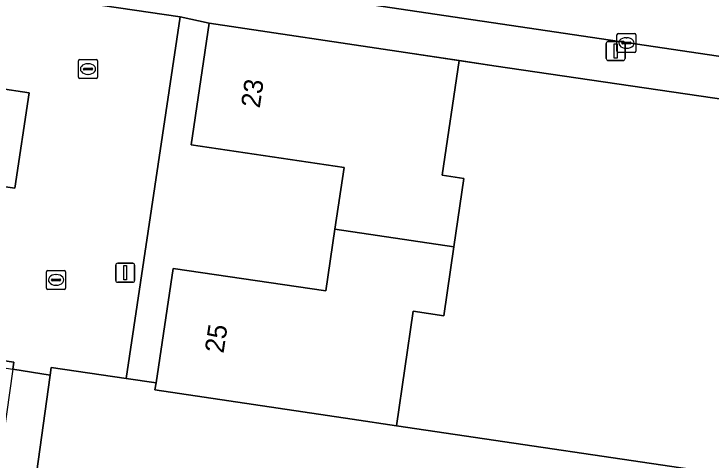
# Model space of a CAD drawing. Extents: x 164148 to 165261, y 382513 to 383432.
# Drawn here: x 164395.92 to 164432.53, y 383053.88 to 383077.34 of the extents above; entities that cross this region are included whole.
import ezdxf

# ---------------------------------------------------------------- set-up
doc = ezdxf.new("R2010")
doc.units = 0
for name, color, linetype in [('IMGEO_Erf', 7, 'Continuous'), ('IMGEO_Fietspad_gesloten', 7, 'Continuous'), ('IMGEO_Groenvoorziening', 7, 'Continuous'), ('IMGEO_Hek', 7, 'Continuous'), ('IMGEO_Kolk', 7, 'Continuous'), ('IMGEO_Lichtmast', 7, 'Continuous'), ('IMGEO_Muur', 7, 'Continuous'), ('IMGEO_Pand', 7, 'Continuous'), ('IMGEO_Pand_nummerreeks', 7, 'Continuous'), ('IMGEO_Parkeervlak_open', 7, 'Continuous'), ('IMGEO_Rijbaan_lokaal_open', 7, 'Continuous'), ('IMGEO_Voetpad_open', 7, 'Continuous')]:
    doc.layers.add(name, color=color, linetype=linetype)

msp = doc.modelspace()

# ---------------------------------------------------------------- linework, layer by layer
at = {"layer": 'IMGEO_Erf'}
msp.add_lwpolyline([(164408.851, 383199.365), (164399.172, 383200.803), (164378.916, 383061.2), (164379.681, 383061.088), (164380.615, 383067.448), (164390.499, 383065.99), (164389.565, 383059.634), (164395.869, 383058.657), (164395.922, 383059.034), (164391.378, 383059.698), (164394.192, 383078.726), (164411.436, 383195.306)], dxfattribs=at)
for points in [[(164401.814, 383058.173), (164403.383, 383057.94), (164404.276, 383063.953), (164412.299, 383062.781), (164412.78, 383066.02), (164413.261, 383069.26), (164405.229, 383070.453), (164406.174, 383076.848), (164404.649, 383077.179)], [(164434.53, 383066.472), (164436.024, 383066.259), (164436.915, 383072.291), (164421.248, 383074.597), (164419.302, 383074.895), (164418.405, 383068.862), (164419.551, 383068.692), (164419.029, 383065.092), (164418.504, 383061.473), (164416.89, 383061.707), (164416.017, 383055.69), (164434.025, 383053.023), (164434.924, 383059.038), (164433.441, 383059.262), (164433.985, 383062.865)]]:
    msp.add_lwpolyline(points, close=True, dxfattribs=at)
at = {"layer": 'IMGEO_Fietspad_gesloten'}
msp.add_lwpolyline([(164397.822, 383058.341), (164395.869, 383058.657), (164394.396, 383048.32), (164396.385, 383048.006)], close=True, dxfattribs=at)
at = {"layer": 'IMGEO_Groenvoorziening'}
msp.add_lwpolyline([(164416.017, 383055.69), (164413.688, 383056.036), (164403.328, 383057.574), (164403.383, 383057.94), (164401.814, 383058.173), (164397.879, 383058.748), (164397.822, 383058.341), (164396.385, 383048.006), (164450.7, 383039.958), (164452.315, 383050.297), (164452.362, 383050.597), (164448.44, 383051.183), (164446.886, 383051.412), (164446.845, 383051.128), (164434.025, 383053.023)], close=True, dxfattribs=at)
at = {"layer": 'IMGEO_Hek'}
msp.add_lwpolyline([(164413.688, 383056.036), (164434.025, 383053.023)], dxfattribs=at)
at = {"layer": 'IMGEO_Kolk'}
for p, q in [((164427.586, 383075.382), (164427.586, 383076.234)), ((164427.661, 383076.308), (164428.513, 383076.308)), ((164428.587, 383076.234), (164428.587, 383075.382)), ((164427.888, 383075.851), (164428.286, 383075.851)), ((164428.074, 383076.088), (164428.099, 383076.088)), ((164427.845, 383075.802), (164427.845, 383075.814)), ((164428.283, 383075.765), (164427.885, 383075.765)), ((164428.097, 383075.528), (164428.072, 383075.528)), ((164428.329, 383075.814), (164428.329, 383075.802)), ((164428.513, 383075.308), (164427.661, 383075.308)), ((164399.311, 383074.014), (164399.311, 383074.866)), ((164399.386, 383074.94), (164400.238, 383074.94)), ((164400.312, 383074.866), (164400.312, 383074.014)), ((164399.57, 383074.434), (164399.57, 383074.446)), ((164400.008, 383074.397), (164399.61, 383074.397)), ((164399.613, 383074.483), (164400.011, 383074.483)), ((164399.799, 383074.72), (164399.824, 383074.72)), ((164400.054, 383074.446), (164400.054, 383074.434)), ((164399.822, 383074.16), (164399.797, 383074.16)), ((164400.238, 383073.94), (164399.386, 383073.94)), ((164397.632, 383062.929), (164397.632, 383063.781)), ((164397.707, 383063.855), (164398.559, 383063.855)), ((164398.633, 383063.781), (164398.633, 383062.929)), ((164397.934, 383063.398), (164398.332, 383063.398)), ((164398.12, 383063.635), (164398.145, 383063.635)), ((164397.891, 383063.349), (164397.891, 383063.361)), ((164398.329, 383063.312), (164397.931, 383063.312)), ((164398.143, 383063.075), (164398.118, 383063.075)), ((164398.375, 383063.361), (164398.375, 383063.349)), ((164398.559, 383062.855), (164397.707, 383062.855))]:
    msp.add_line(p, q, dxfattribs=at)
for points in [[(164427.586, 383075.382), (164427.586, 383076.234)], [(164427.661, 383076.308), (164428.513, 383076.308)], [(164428.587, 383076.234), (164428.587, 383075.382)], [(164428.513, 383075.308), (164427.661, 383075.308)], [(164399.311, 383074.014), (164399.311, 383074.866)], [(164399.386, 383074.94), (164400.238, 383074.94)], [(164400.312, 383074.866), (164400.312, 383074.014)], [(164400.238, 383073.94), (164399.386, 383073.94)], [(164397.632, 383062.929), (164397.632, 383063.781)], [(164397.707, 383063.855), (164398.559, 383063.855)], [(164398.633, 383063.781), (164398.633, 383062.929)], [(164398.559, 383062.855), (164397.707, 383062.855)]]:
    msp.add_lwpolyline(points, dxfattribs=at)
for centre, radius, start, end in [((164427.663, 383076.232), 0.0765, 91.552, 178.448), ((164427.663, 383076.232), 0.0765, 91.552, 178.448), ((164428.511, 383076.232), 0.0765, 1.552, 88.448), ((164428.511, 383076.232), 0.0765, 1.552, 88.448), ((164427.885, 383075.811), 0.0403, 85.8775, 175.7526), ((164428.29, 383075.813), 0.0386, 1.7309, 96.639), ((164427.882, 383075.801), 0.0366, 178.938, 274.7102), ((164428.286, 383075.808), 0.043, 264.8664, 352.4533), ((164427.663, 383075.384), 0.0765, 181.552, 268.448), ((164427.663, 383075.384), 0.0765, 181.552, 268.448), ((164428.511, 383075.384), 0.0765, 271.552, 358.448), ((164428.511, 383075.384), 0.0765, 271.552, 358.448), ((164399.388, 383074.864), 0.0765, 91.552, 178.448), ((164399.388, 383074.864), 0.0765, 91.552, 178.448), ((164400.236, 383074.864), 0.0765, 1.552, 88.448), ((164400.236, 383074.864), 0.0765, 1.552, 88.448), ((164399.61, 383074.443), 0.0403, 85.8775, 175.7526), ((164399.607, 383074.433), 0.0366, 178.938, 274.7102), ((164400.011, 383074.44), 0.043, 264.8664, 352.4533), ((164400.015, 383074.445), 0.0386, 1.7309, 96.639), ((164399.388, 383074.016), 0.0765, 181.552, 268.448), ((164399.388, 383074.016), 0.0765, 181.552, 268.448), ((164400.236, 383074.016), 0.0765, 271.552, 358.448), ((164400.236, 383074.016), 0.0765, 271.552, 358.448), ((164397.709, 383063.779), 0.0765, 91.552, 178.448), ((164397.709, 383063.779), 0.0765, 91.552, 178.448), ((164398.557, 383063.779), 0.0765, 1.552, 88.448), ((164398.557, 383063.779), 0.0765, 1.552, 88.448), ((164397.931, 383063.358), 0.0403, 85.8775, 175.7526), ((164398.336, 383063.36), 0.0386, 1.7309, 96.639), ((164397.928, 383063.348), 0.0366, 178.938, 274.7102), ((164398.332, 383063.355), 0.043, 264.8664, 352.4533), ((164397.709, 383062.931), 0.0765, 181.552, 268.448), ((164397.709, 383062.931), 0.0765, 181.552, 268.448), ((164398.557, 383062.931), 0.0765, 271.552, 358.448), ((164398.557, 383062.931), 0.0765, 271.552, 358.448)]:
    msp.add_arc(centre, radius, start, end, dxfattribs=at)
for centre, major_axis, ratio, start_param, end_param in [((164428.073, 383075.808), (-0.387, 0.002), 0.722429, 4.712389, 7.853982), ((164428.098, 383075.808), (-0.39, 0.002), 0.717154, 1.570796, 4.712389), ((164399.798, 383074.44), (-0.387, 0.002), 0.722429, 4.712389, 7.853982), ((164399.823, 383074.44), (-0.39, 0.002), 0.717154, 1.570796, 4.712389), ((164398.119, 383063.355), (-0.387, 0.002), 0.722429, 4.712389, 7.853982), ((164398.144, 383063.355), (-0.39, 0.002), 0.717154, 1.570796, 4.712389)]:
    msp.add_ellipse(centre, major_axis=major_axis, ratio=ratio, start_param=start_param, end_param=end_param, dxfattribs=at)
at = {"layer": 'IMGEO_Lichtmast'}
for p, q in [((164427.124, 383075.889), (164427.914, 383075.889)), ((164427.914, 383075.889), (164427.124, 383075.889)), ((164427.024, 383074.989), (164427.024, 383075.789)), ((164427.024, 383075.789), (164427.024, 383074.989)), ((164428.014, 383075.789), (164428.014, 383074.989)), ((164428.014, 383074.989), (164428.014, 383075.789)), ((164427.914, 383074.889), (164427.124, 383074.889)), ((164427.124, 383074.889), (164427.914, 383074.889)), ((164401.369, 383064.229), (164402.159, 383064.229)), ((164402.159, 383064.229), (164401.369, 383064.229)), ((164401.269, 383063.329), (164401.269, 383064.129)), ((164401.269, 383064.129), (164401.269, 383063.329)), ((164402.259, 383064.129), (164402.259, 383063.329)), ((164402.259, 383063.329), (164402.259, 383064.129)), ((164402.159, 383063.229), (164401.369, 383063.229)), ((164401.369, 383063.229), (164402.159, 383063.229))]:
    msp.add_line(p, q, dxfattribs=at)
for points in [[(164427.444, 383075.764), (164427.594, 383075.764), (164427.594, 383075.014), (164427.444, 383075.014), (164427.444, 383075.764)], [(164401.689, 383064.104), (164401.839, 383064.104), (164401.839, 383063.354), (164401.689, 383063.354), (164401.689, 383064.104)]]:
    msp.add_lwpolyline(points, dxfattribs=at)
for centre, start, end in [((164427.124, 383075.789), 90, 180), ((164427.124, 383075.789), 90, 180), ((164427.914, 383075.789), 0, 90), ((164427.914, 383075.789), 360, 90), ((164427.124, 383074.989), 180, 270), ((164427.124, 383074.989), 180, 270), ((164427.914, 383074.989), 270, 0), ((164427.914, 383074.989), 270, 0), ((164401.369, 383064.129), 90, 180), ((164401.369, 383064.129), 90, 180), ((164402.159, 383064.129), 0, 90), ((164402.159, 383064.129), 360, 90), ((164401.369, 383063.329), 180, 270), ((164401.369, 383063.329), 180, 270), ((164402.159, 383063.329), 270, 0), ((164402.159, 383063.329), 270, 0)]:
    msp.add_arc(centre, 0.1, start, end, dxfattribs=at)
at = {"layer": 'IMGEO_Muur'}
msp.add_lwpolyline([(164416.488, 383075.314), (164421.248, 383074.597)], dxfattribs=at)
at = {"layer": 'IMGEO_Pand'}
for points in [[(164419.302, 383074.895), (164416.488, 383075.314), (164406.174, 383076.848), (164405.229, 383070.453), (164413.261, 383069.26), (164412.78, 383066.02), (164419.029, 383065.092), (164419.551, 383068.692), (164418.405, 383068.862)], [(164416.89, 383061.707), (164418.504, 383061.473), (164419.029, 383065.092), (164412.78, 383066.02), (164412.299, 383062.781), (164404.276, 383063.953), (164403.383, 383057.94), (164403.328, 383057.574), (164413.688, 383056.036), (164416.017, 383055.69)]]:
    msp.add_lwpolyline(points, close=True, dxfattribs=at)
at = {"layer": 'IMGEO_Parkeervlak_open'}
msp.add_lwpolyline([(164395.967, 383068.172), (164396.717, 383073.186), (164395.08, 383073.431), (164394.339, 383068.414)], close=True, dxfattribs=at)
at = {"layer": 'IMGEO_Rijbaan_lokaal_open'}
msp.add_lwpolyline([(164405.11, 383079.283), (164405.729, 383079.159), (164450.54, 383072.506), (164451.276, 383072.42)], dxfattribs=at)
at = {"layer": 'IMGEO_Voetpad_open'}
for points in [[(164411.436, 383195.306), (164394.192, 383078.726), (164404.649, 383077.179), (164406.174, 383076.848), (164416.488, 383075.314), (164419.302, 383074.895), (164421.248, 383074.597), (164436.915, 383072.291), (164449.7, 383070.397), (164451.274, 383070.164), (164461.739, 383068.623), (164479.002, 383185.851)], [(164451.299, 383071.338), (164451.276, 383072.42), (164450.54, 383072.506), (164405.729, 383079.159), (164405.11, 383079.283), (164404.845, 383078.202)]]:
    msp.add_lwpolyline(points, dxfattribs=at)
for points in [[(164404.649, 383077.179), (164394.192, 383078.726), (164391.378, 383059.698), (164395.922, 383059.034), (164395.869, 383058.657), (164397.822, 383058.341), (164397.879, 383058.748), (164401.814, 383058.173)], [(164395.967, 383068.172), (164394.339, 383068.414), (164395.08, 383073.431), (164396.717, 383073.186)]]:
    msp.add_lwpolyline(points, close=True, dxfattribs=at)

# ---------------------------------------------------------------- texts
at = {"layer": 'IMGEO_Pand_nummerreeks'}
for s, rotation, p in [('23', 81.6006, (164408.826, 383072.357)), ('25', 81.5548, (164406.925, 383059.467))]:
    msp.add_text(s, height=1, rotation=rotation, dxfattribs=at).set_placement(p)

doc.saveas('drawing.dxf')
